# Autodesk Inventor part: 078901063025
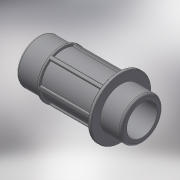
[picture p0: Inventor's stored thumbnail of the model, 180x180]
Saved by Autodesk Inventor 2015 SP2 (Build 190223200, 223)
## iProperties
Created: 2018-02
Part Number: 078901063025
Material: Generic
Description: PLASSON THREADED MALE ADAPTOR 63-2.1/2"
Document SubType Name: Modeling
Designer: KIM
Density: 1 g/cm^3
Appearance: Default
Author: KIM
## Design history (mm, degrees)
derived "078901.ipt"
feature "Solid1::078901.ipt"
tag "TaggingFeature1"
body "Solid1"
other parameters: "d4" = 3.7592, "d14" = 6.01472, "d15" = 3.00736, "d17" = 0, "d20" = 360 deg, "d40" = 29, "d41" = 75.184, "d45" = 82.7024, "d46" = 52.6288, "d47" = 2.9, "d77" = 116, "d78" = 63, "d85" = 0.75184, "d91" = 23.2, "d103" = 26.68, "d104" = 83, "d105" = 0.75184, "R_" = 75.184, "E_" = 83, "l_2" = 29, "l_" = 116, "d_" = 63
